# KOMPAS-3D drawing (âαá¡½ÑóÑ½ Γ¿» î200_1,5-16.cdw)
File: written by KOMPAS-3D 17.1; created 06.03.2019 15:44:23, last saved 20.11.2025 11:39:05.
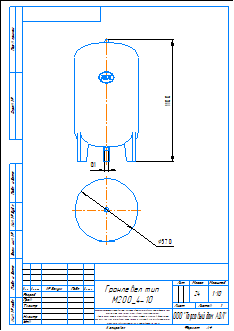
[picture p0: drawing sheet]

Sheet 1: A4, portrait

Title block, sheet 1: name: Гранлевел тип / М200_4-10; mass: 24; sheets: 1; sheet format: A4; stored path: C:\Users\kka\KOMPAS_Work\!Trash\ГРАНЛЕВЕЛ тип А Расширительный бак\KOMPAS 2D\Гранлевел тип А100_1,5-16.cdw

Views: Спереди 1, Спереди, Проекционный вид 2
Referenced files in C:\Users\mipv\Desktop\Тип А\SAT\: Гранлевел тип А200_4-10.a3d
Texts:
  kka
  adl
  Гранлевел тип А200_4-10
  Рама для чертежей
  Лит-Масса-Масштаб
  Материал-Предприятие
  Масштаб
  Изм.
  Лист
  № докум.
  Подп.
  Дата
  Лит.
  Разраб.
  Пров.
  Т.контр.
  Листов
  Внимание! Данный продукт является объектом авторского права ООО «Торговый Дом АДЛ».
  Запрещается изменение, копирование, распространение
  (в том числе путем копирования на другие сайты и ресурсы в Интернете)
  или любое иное использование информации и объектов без предварительного
  согласия правообладателя (ООО «Торговый Дом АДЛ»).
  Н.контр.
  Утв.
  ООО "Торговый дом АДЛ"
  Изменение
  Номер документа
  Подпись
  Обозначение документа
  Наименование изделия
  Масса изделия по ГОСТ 2.109-73
  Порядковый номер листа
  Общее количество листов в документе
  Характер работы, выполненной лицом, подписавшим документ
  Наименование или индекс предприятия, выпускающего документ
  Инв. № подл.
  Подп. и дата
  Взам. инв. №
  Инв. № дубл.
  Инвентарный номер подлинника по ГОСТ 2.501-68
  Подпись принявшего подлинник в отдел технической документации
  Инвентарный номер подлинника, взамен которого выпущен данный подлинник
  Инвентарный номер дубликата по ГОСТ 2.502-68
  Подпись принявшего дубликат в отдел технической документации
  Справ. №
  Перв. примен.
  Обозначение документа, взамен или на основании которого выпущен данный документ
  Обозначение документа, в котором впервые записан данный документ
  Подпись лица, копировавшего чертеж
  Обозначение формата листа
  !Рама для чертежа
Dimensions and other numbers on the sheet: 1100; 570; 1:10; 1; 24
